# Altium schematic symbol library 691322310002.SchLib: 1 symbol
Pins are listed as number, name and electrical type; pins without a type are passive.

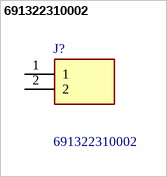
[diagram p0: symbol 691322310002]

## 691322310002
designator J?
WR-TBL Terminal block - PCB Header - THT Serie 322 - 3,81mm pitch - Monoblock THT - Green - Horizontal PCB Header 02p; Manufacturer_Name: Wurth Elektronik; Geometry.Height: 7.2mm
footprint SHDRRA2W95P0X381_1X2_881X920X720P
pins: 1, 2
